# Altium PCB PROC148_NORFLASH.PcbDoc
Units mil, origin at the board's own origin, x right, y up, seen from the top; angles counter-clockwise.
Board outline 790 x 790 mil, 6 copper layers (Top Layer, GND1, Signal Layer 1, Signal Layer 2, PWR/GND2, Bottom Layer), stack 65.134 mil thick; 36 components, 63 nets, 233 pads, 102 vias.
Unrouted connection lines stored in the file: 1.
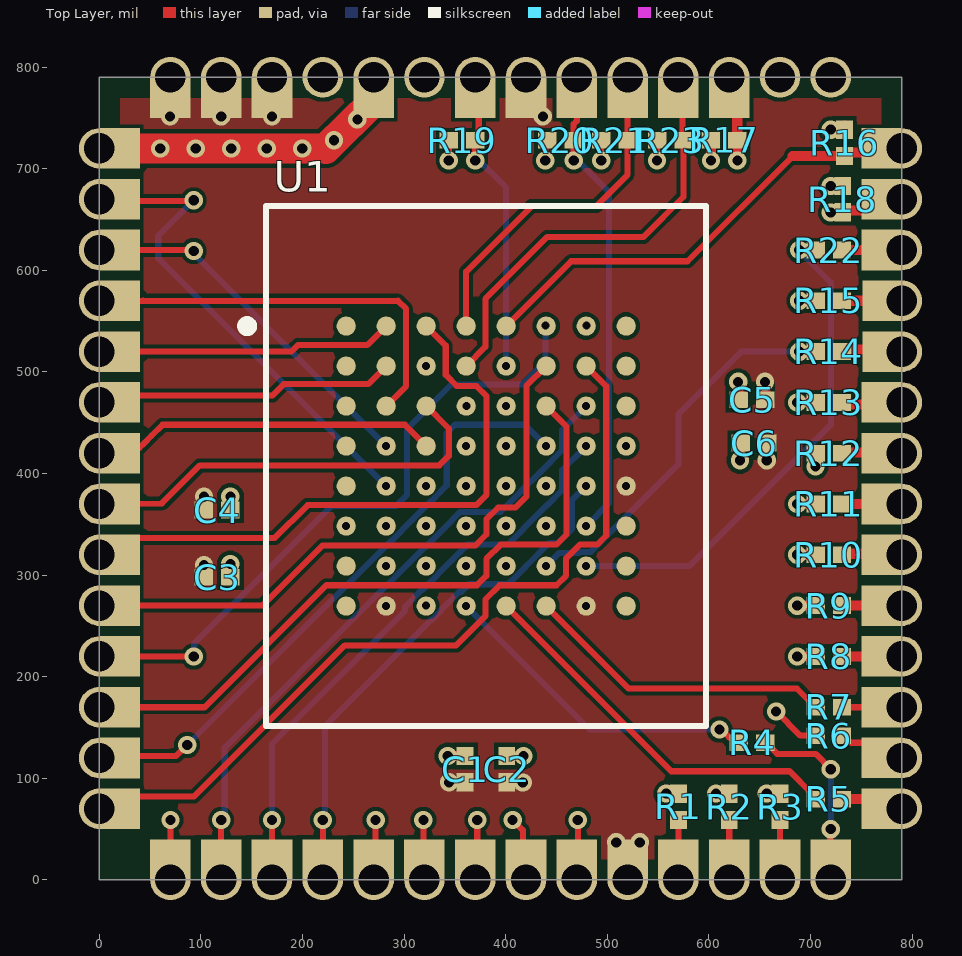
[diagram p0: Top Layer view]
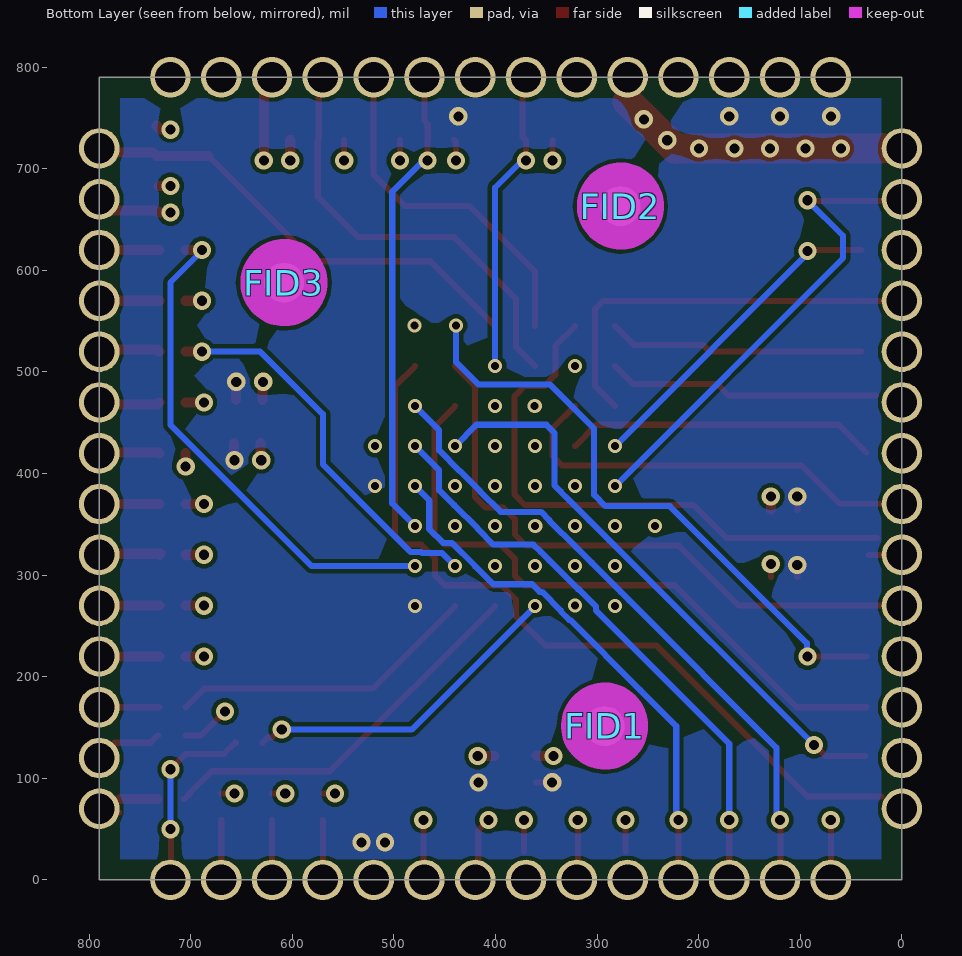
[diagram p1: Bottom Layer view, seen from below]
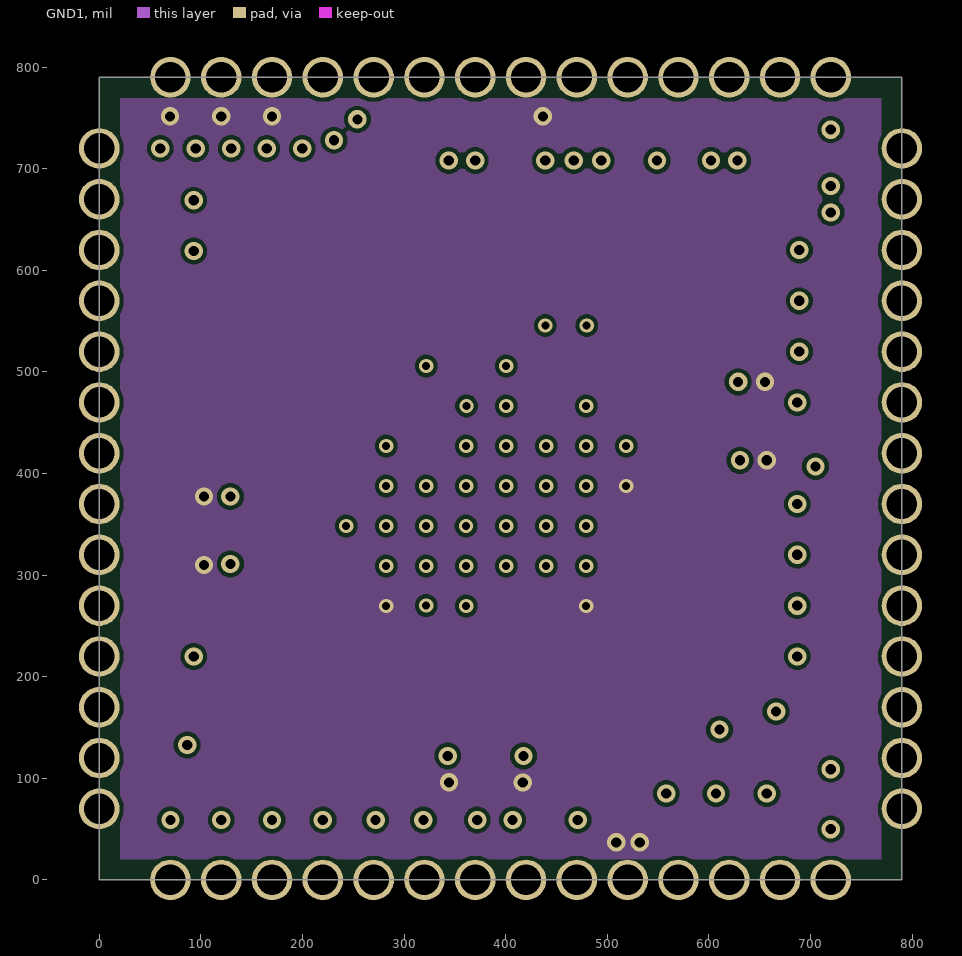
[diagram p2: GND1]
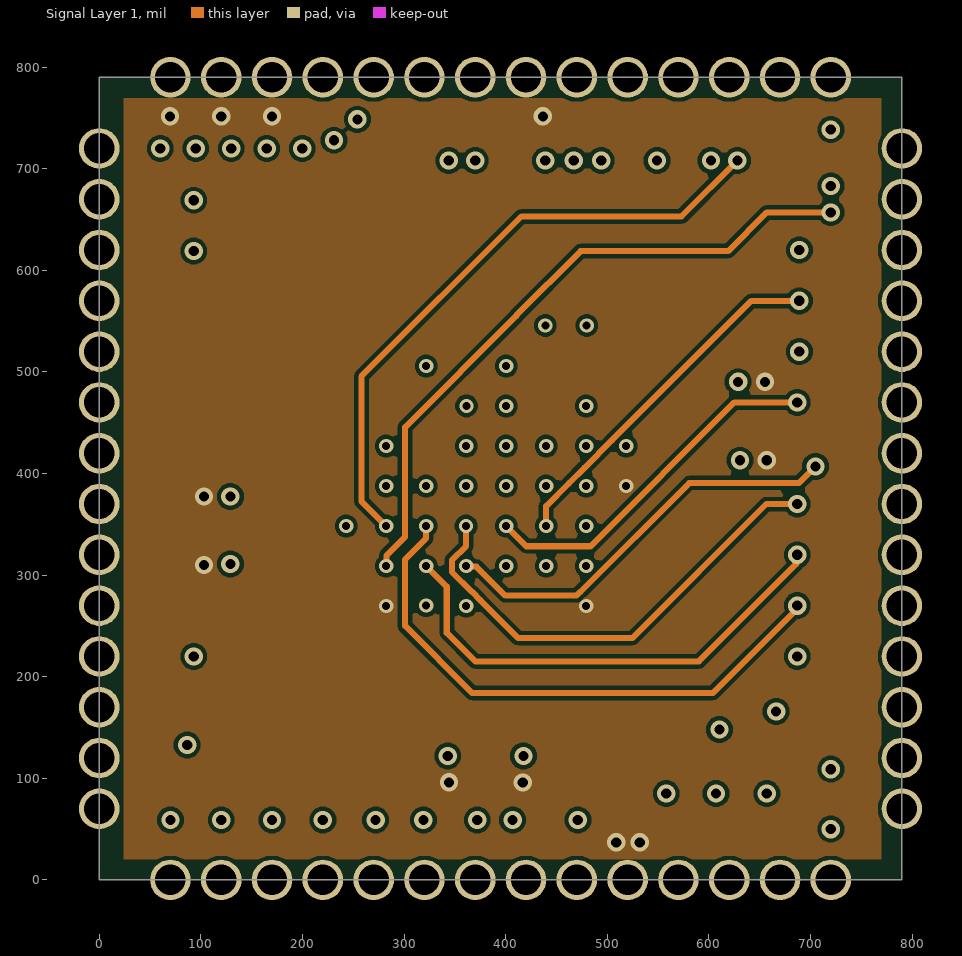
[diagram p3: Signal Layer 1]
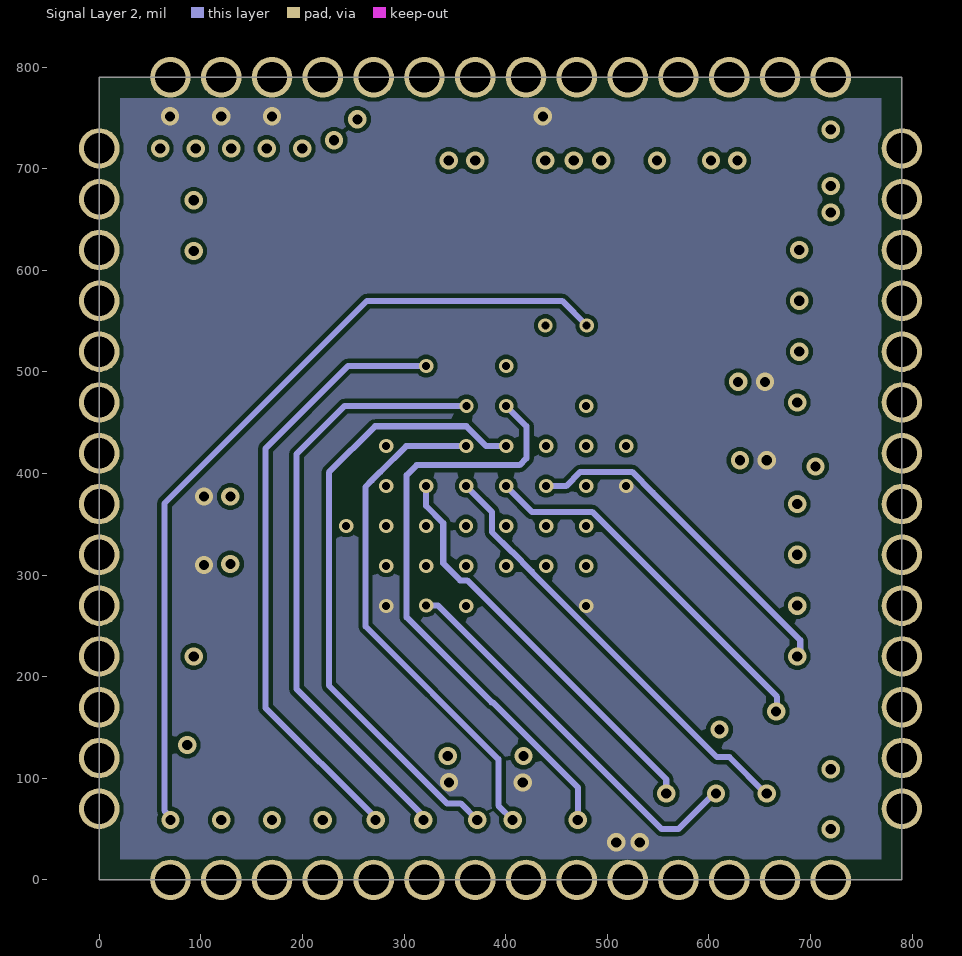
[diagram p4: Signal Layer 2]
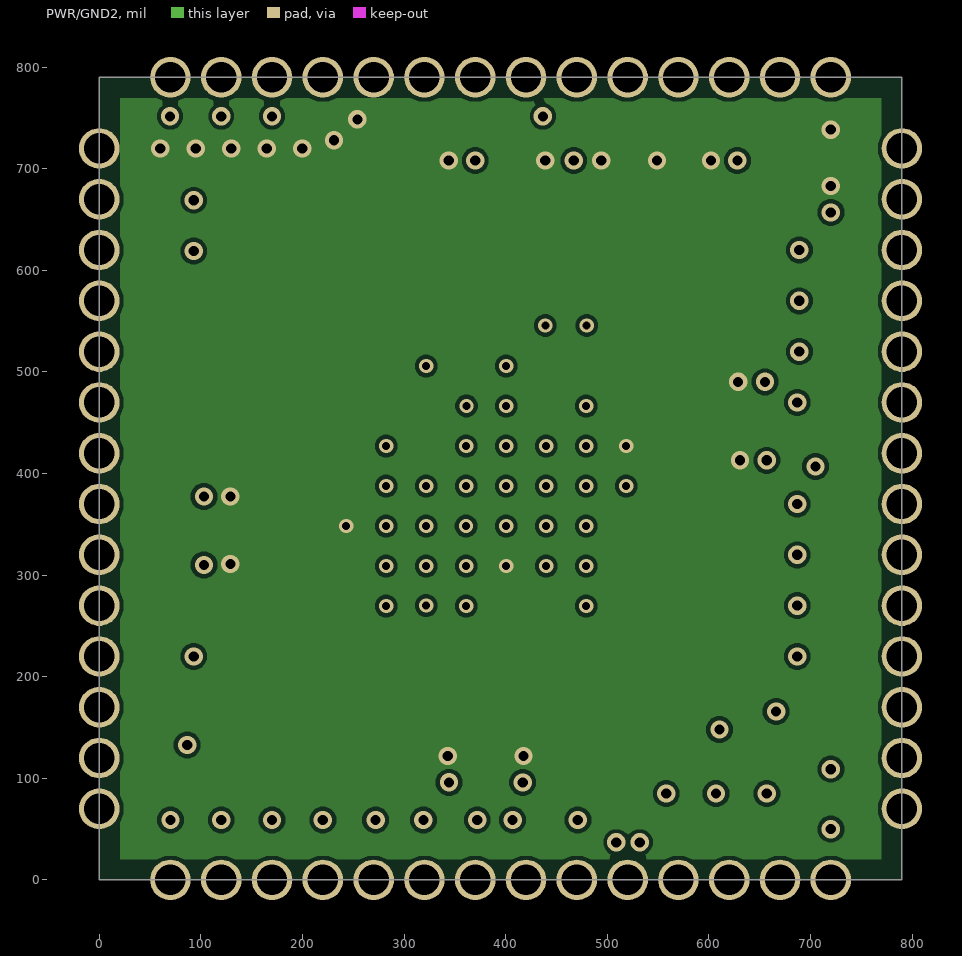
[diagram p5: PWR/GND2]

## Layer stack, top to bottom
Top Solder: solder mask 0.4, Solder Resist, Dk 3.5
Top Layer: signal copper 0.689
Dielectric 1: prepreg 3.7, FR-4, Dk 4.1
GND1: signal copper 0.689
Dielectric 3: prepreg 2.8, PP-006, Dk 4.1
Signal Layer 1: signal copper 0.689
Dielectric1: core 48, FR-4, Dk 4.8
Signal Layer 2: signal copper 0.689
Dielectric 4: prepreg 2.8, PP-006, Dk 4.1
PWR/GND2: signal copper 0.689
Dielectric 2: prepreg 3.7, FR-4, Dk 4.1
Bottom Layer: signal copper 0.689
Bottom Solder: solder mask 0.4, Solder Resist, Dk 3.5

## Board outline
0,0 790,0 790,790 0,790

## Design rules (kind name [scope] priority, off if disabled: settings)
AcuteAngle [All] p1: minimum=4.50000000000000E+0001 checktracksonly=FALSE
AssemblyTestPointUsage [All] p1: valid=2
BoardOutlineClearance BoardOutlineClearance_MountingHoles [OnCopper and InComponentClass('Mounting Holes')] p1: gap=39.37 ignorepadtopadclearanceinfootprint=FALSE
BoardOutlineClearance BoardOutlineClearance_Poly [OnCopper and IsPoly] p2: gap=20 ignorepadtopadclearanceinfootprint=FALSE
BoardOutlineClearance [OnCopper and Not InComponentClass('Logo') and not InComponentClass('FiducialMark') and not InRegion(1000,500,4000,800) and not InPoly] p3: gap=40 ignorepadtopadclearanceinfootprint=FALSE
Clearance Clearance_Keepouts [((IsTrack Or IsArc) And Not InPoly) And IsFree and IsKeepOut vs ((IsTrack Or IsArc) And Not InPoly) And IsFree and IsKeepOut] p1: gap=0 ignorepadtopadclearanceinfootprint=FALSE
Clearance Clearance_Poly [InPolygon] p2: gap=4 ignorepadtopadclearanceinfootprint=TRUE except(10: Arc-Arc Arc-Track Arc-SMDPad Arc-THPad Arc-Text Arc-Hole Track-Track Track-SMDPad Track-THPad Track-Text Track-Hole SMDPad-SMDPad SMDPad-THPad SMDPad-Text SMDPad-Hole THPad-THPad THPad-Text THPad-Hole Text-Text Text-Hole)
Clearance Clearance_FiducialMark [IsKeepOut and InComponentClass('FiducialMark') vs IsPad and InComponentClass('FiducialMark')] p3: gap=0 ignorepadtopadclearanceinfootprint=FALSE
Clearance [All] p4: gap=4 ignorepadtopadclearanceinfootprint=TRUE
ComponentClearance ComponentClearance_MountingHoles_FiducialMarks [InComponentClass('Mounting Holes') vs InComponentClass('FiducialMark')] p1: gap=50 collisioncheckmode=3 verticalgap=10 showdistances=FALSE
ComponentClearance ComponentClearance_Shunt [InComponentClass('Header') vs InComponentClass('Shunt')] p2: gap=0 collisioncheckmode=3 verticalgap=0 showdistances=FALSE
ComponentClearance ComponentClearance_Logo [InComponentClass('Logo')] p3: gap=30 collisioncheckmode=3 verticalgap=10 showdistances=FALSE
ComponentClearance ComponentClearance_ScrewToNut [(HasFootprint('NY PMS 440 0025 PH')) vs (HasFootprint('Keystone_1902C'))] p4: gap=5 collisioncheckmode=3 verticalgap=10 showdistances=FALSE
ComponentClearance ComponentClearance_MountingHoles [InComponentClass('Mounting Holes')] p5: gap=100 collisioncheckmode=3 verticalgap=100000 showdistances=FALSE
ComponentClearance ComponentClearance_SmallPassives [HasFootprint('0201*') or HasFootprint('0402*') or HasFootprint('0508') or HasFootprint('0603*') or HasFootprint('0612') or HasFootprint('0805*') or HasFootprint('0815*') or HasFootprint('0830*') or HasFootprint('1206*') or HasFootprint('1210*') or HasFootprint('1808*') or HasFootprint('1812*') or HasFootprint('1825*') or HasFootprint('2010*') or HasFootprint('2220*') or HasFootprint('2225*') or HasFootprint('2512*') or HasFootprint('2728*') or HasFootprint('3518*') vs HasFootprint('0201*') or HasFootprint('0402*') or HasFootprint('0508') or HasFootprint('0603*') or HasFootprint('0612') or HasFootprint('0805*') or HasFootprint('0815*') or HasFootprint('0830*') or HasFootprint('1206*') or HasFootprint('1210*') or HasFootprint('1808*') or HasFootprint('1812*') or HasFootprint('1825*') or HasFootprint('2010*') or HasFootprint('2220*') or HasFootprint('2225*') or HasFootprint('2512*') or HasFootprint('2728*') or HasFootprint('3518*')] p6: gap=14.96 collisioncheckmode=3 verticalgap=10 showdistances=FALSE
ComponentClearance ComponentClearance_THtoSMT [IsThruComponent vs IsSMTComponent] p7: gap=30 collisioncheckmode=3 verticalgap=30 showdistances=FALSE
ComponentClearance ComponentClearance_THtoTH [IsThruComponent vs IsThruComponent] p8: gap=20 collisioncheckmode=3 verticalgap=30 showdistances=FALSE
ComponentClearance [All] p9: gap=20 collisioncheckmode=3 verticalgap=10 showdistances=FALSE
DiffPairsRouting [All] p1: maxlimit=100 minlimit=10 mostfreqgap=10 toplayer_minwidth=15 toplayer_maxwidth=15 toplayer_prefwidth=15 midlayer1_minwidth=15 midlayer1_maxwidth=15 midlayer1_prefwidth=15 midlayer2_minwidth=15 midlayer2_maxwidth=15 midlayer2_prefwidth=15 midlayer3_minwidth=15 midlayer3_maxwidth=15 midlayer3_prefwidth=15 midlayer4_minwidth=15 midlayer4_maxwidth=15 midlayer4_prefwidth=15 bottomlayer_minwidth=15 bottomlayer_maxwidth=15 bottomlayer_prefwidth=15 maxuncoupledlength=1000
FabricationTestPointUsage TestPointUsage [All] p1: valid=2 allowmultiple=FALSE
FabricationTestpoint Testpoint [All] p1: side=3 testpointundercomponent=TRUE minsize=40 maxsize=100 preferedsize=60 minholesize=0 maxholesize=40 preferedholesize=32 testpointgrid=1 allowsidetop=TRUE allowsidebottom=TRUE usegrid=TRUE gridtolerance=0.01
FanoutControl Fanout_LCC [IsLCC] p1: bgadir=Out bgaviamode=Centered fanoutstyle=Auto fanoutdirection=Alternating viagrid=1 // Fanout_LCC (Default Rule)
FanoutControl Fanout_BGA [IsBGA] p2: bgadir=Out bgaviamode=Centered fanoutstyle=Auto fanoutdirection=Alternating viagrid=1 // Fanout_BGA (Default Rule)
FanoutControl Fanout_Default [All] p4: bgadir=Out bgaviamode=Centered fanoutstyle=Auto fanoutdirection=Alternating viagrid=1 // Fanout_Default (Default Rule)
FanoutControl Fanout_Small [(CompPinCount < 5)] p5: bgadir=Out bgaviamode=Centered fanoutstyle=Auto fanoutdirection=OutThenIn viagrid=1 // Fanout_Small (Default Rule)
HoleSize [All] p1: absolutevalues=TRUE maxlimit=251 minlimit=7 maxpercent=80.000 minpercent=20.000
HoleToHoleClearance [All] p1: gap=6 allowstackedmicrovias=TRUE
MinimumAnnularRing MinimumAnnularRing_ThermalPadVias [IsVia and InAnyComponent] p1: minimumring=5.91
MinimumAnnularRing [All] p2: minimumring=3
MinimumSolderMaskSliver MinimumSolderMaskSliver_Logo [InComponentClass('Logo') vs InComponentClass('Logo')] p1: minsoldermaskwidth=0.7
MinimumSolderMaskSliver [All] p2: minsoldermaskwidth=3
PlaneConnect [All] p1: planeconnectstyle=Relief reliefexpansion=10 reliefentries=4 reliefconductorwidth=10 reliefairgap=10
PolygonConnect [All] p1: connectstyle=Direct reliefconductorwidth=10 reliefentries=4 polygonreliefangle="90 Angle" airgapwidth=10
RoutingVias ThermalPadVias [IsVia and InAnyComponent] p1: holewidth=7.87 width=19.68 viastyle="Through Hole" minholewidth=7.87 minwidth=19.68 maxholewidth=12.99 maxwidth=23.62
RoutingVias [All] p2: holewidth=16 width=34 viastyle="Through Hole" minholewidth=7.87 minwidth=14 maxholewidth=40 maxwidth=65
SilkToBoardRegionClearance [Not ((IsComment or IsDesignator) And (Hide <> 'False')) and not InRegion(1000,500,4000,800)] p1:
SilkToSilkClearance SilkToSilkClearance_Pb-FreeLogo [(HasFootprint('Pb-Free_Overlay_Medium') OR HasFootprint('Pb-Free_Overlay_Small')) vs (HasFootprint('Pb-Free_Overlay_Medium') OR HasFootprint('Pb-Free_Overlay_Small'))] p1: silktosilkclearance=0
SilkToSilkClearance [All] p2: silktosilkclearance=3.94
SilkToSolderMaskClearance SilkToComponentPadClearance [(IsPad or IsFill or IsRegion) and InAnycomponent] p1: minsilkscreentomaskgap=5 clearancetoexposedcopper=TRUE
SilkToSolderMaskClearance "Silk to Solder Mask Opening" [All] p2: minsilkscreentomaskgap=3 clearancetoexposedcopper=FALSE
SolderMaskExpansion [All] p1: expansion=1.97 istentingtop=FALSE
UnRoutedNet [All] p1: checkbadconnections=TRUE
Width [All] p1: maxlimit=100 minlimit=6 preferedwidth=10 checkconnectedcopper=TRUE
13 further rules are at their usual default settings.

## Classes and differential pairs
component class PROC148_NORFLASH: C1 C2 C3 C4 C5 C6 R1 R2 R3 R4 R5 R6 R7 R8 R9 R10 R11 R12 R13 R14 R15 R16 R17 R19 R20 R21 R22 R23 U1
component class PROC148_NORFLASH_Hardware: FID1 FID2 FID3 ZZ2 ZZ3 ZZ4
component class FiducialMark: FID1 FID2 FID3
component class AssemblyNote: ZZ2 ZZ3 ZZ4

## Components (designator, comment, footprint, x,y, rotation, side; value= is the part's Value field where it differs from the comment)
C1 "GRM033R61C104KE84D" 0201_033 360,109 r270 top value=0.1uF
C2 "GRM033R61C103KA12D" 0201_033 401,109 r270 top value=0.01uF
C3 "GRM033R61C103KA12D" 0201_033 116,298 r180 top value=0.01uF
C4 "GRM033R61C104KE84D" 0201_033 116,364 r180 top value=0.1uF
C5 "GRM033R61C103KA12D" 0201_033 642.47,472.53 r0 top value=0.01uF
C6 "GRM033R61C104KE84D" 0201_033 644.48,430 r0 top value=0.1uF
FID1 "Fiducial" Fiducial10-20 292.6,151.41 r180 bottom
FID2 "Fiducial" Fiducial10-20 277.05,663.22 r180 bottom
FID3 "Fiducial" Fiducial10-20 608.24,587.88 r180 bottom
R1 "ERJ-1GNJ220C" 0201 570,72 r270 top value=22
R2 "ERJ-1GNJ220C" 0201 620,72 r270 top value=22
R3 "ERJ-1GNJ220C" 0201 670,72 r270 top value=22
R4 "ERJ-1GNJ220C" 0201 642.47,135.01 r0 top value=22
R5 "ERJ-1GNJ220C" 0201 718,79.5 r0 top value=22
R6 "ERJ-1GNJ220C" 0201 718,142 r0 top value=22
R7 "ERJ-1GNJ220C" 0201 718,170 r0 top value=22
R8 "ERJ-1GNJ220C" 0201 718,220 r0 top value=22
R9 "ERJ-1GNJ220C" 0201 718,270 r0 top value=22
R10 "ERJ-1GNJ220C" 0201 718,320 r0 top value=22
R11 "ERJ-1GNJ220C" 0201 718,370 r0 top value=22
R12 "ERJ-1GNJ220C" 0201 718,420 r0 top value=22
R13 "ERJ-1GNJ220C" 0201 718,470 r0 top value=22
R14 "ERJ-1GNJ220C" 0201 718,520 r0 top value=22
R15 "ERJ-1GNJ220C" 0201 718,570 r0 top value=22
R16 "RC0201JS-7D10KL" 0201 733.51,725.49 r90 top value=10k
R17 "RC0201JS-7D10KL" 0201 615,728 r180 top value=10k
R18 "RC0201JS-7D10KL" 0201 731.71,670 r90 top value=10k
R19 "RC0201JS-7D10KL" 0201 357,728 r180 top value=10k
R20 "RC0201JS-7D10KL" 0201 453.74,728 r180 top value=10k
R21 "RC0201JS-7D10KL" 0201 507,728 r180 top value=10k
R22 "ERJ-1GNJ220C" 0201 718,620 r0 top value=22
R23 "RC0201JS-7D10KL" 0201 562,728 r180 top value=10k
U1 "MT28EW256ABA1LPC-0SIT" FP-MT28EW256ABA1LPC-0SIT_LBGA64-IPC_C 380.8,407.32 r0 top
ZZ2 "These assemblies are ESD sensitive, ESD precautions shall be observed." AssemblyNote -81,2104 r0 top
ZZ3 "These assemblies must be clean and free from flux and all contaminants. Use of no clean flux is not acceptable." AssemblyNote -81,2004 r0 top
ZZ4 "These assemblies must comply with workmanship standards IPC-A-610 Class 2, unless otherwise specified." AssemblyNote -81,1904 r0 top

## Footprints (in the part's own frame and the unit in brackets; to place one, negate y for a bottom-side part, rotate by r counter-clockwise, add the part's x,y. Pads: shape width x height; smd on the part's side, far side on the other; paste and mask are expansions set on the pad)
0201 [mm] "Data from Kemet datasheet CC101_COM dated 7/28/11"
  rect 0.46x0.42 smd mask+0.048: 1(-0.33,0) 2(0.33,0)
  body extent -0.31,-0.16 0.31,0.16, height 0.26
0201_033 [mm] "SMD, 2-Leads, Height 0.33mm"
  rect 0.46x0.42 smd mask+0.048: 1(-0.33,0) 2(0.33,0)
  body extent -0.31,-0.16 0.31,0.16, height 0.33
AssemblyNote [mil] "Assembly Note"
Fiducial10-20 [mm]
  round 1 smd mask+0.5: 1(0,0)
  Top Layer keep-out circle w1.178: c0,0 r0.5
FP-MT28EW256ABA1LPC-0SIT_LBGA64-IPC_C [mm]
  round 0.48 smd paste+0 mask+0: A1(-3.5,3.5) A2(-2.5,3.5) A3(-1.5,3.5) A4(-0.5,3.5) A5(0.5,3.5) A6(1.5,3.5) A7(2.5,3.5) A8(3.5,3.5) B1(-3.5,2.5) B2(-2.5,2.5) B3(-1.5,2.5) B4(-0.5,2.5) B5(0.5,2.5) B6(1.5,2.5) B7(2.5,2.5) B8(3.5,2.5) C1(-3.5,1.5) C2(-2.5,1.5) C3(-1.5,1.5) C4(-0.5,1.5) C5(0.5,1.5) C6(1.5,1.5) C7(2.5,1.5) C8(3.5,1.5) D1(-3.5,0.5) D2(-2.5,0.5) D3(-1.5,0.5) D4(-0.5,0.5) D5(0.5,0.5) D6(1.5,0.5) D7(2.5,0.5) D8(3.5,0.5) E1(-3.5,-0.5) E2(-2.5,-0.5) E3(-1.5,-0.5) E4(-0.5,-0.5) E5(0.5,-0.5) E6(1.5,-0.5) E7(2.5,-0.5) E8(3.5,-0.5) F1(-3.5,-1.5) F2(-2.5,-1.5) F3(-1.5,-1.5) F4(-0.5,-1.5) F5(0.5,-1.5) F6(1.5,-1.5) F7(2.5,-1.5) F8(3.5,-1.5) G1(-3.5,-2.5) G2(-2.5,-2.5) G3(-1.5,-2.5) G4(-0.5,-2.5) G5(0.5,-2.5) G6(1.5,-2.5) G7(2.5,-2.5) G8(3.5,-2.5) H1(-3.5,-3.5) H2(-2.5,-3.5) H3(-1.5,-3.5) H4(-0.5,-3.5) H5(0.5,-3.5) H6(1.5,-3.5) H7(2.5,-3.5) H8(3.5,-3.5)
  silkscreen extent -6.1,-6.5 5.5,6.5, body extent -5.6,-6.6 5.6,6.6, height 0.25

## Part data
C1 C4 C6: library part CMP-0009717-2, "CAP, CERM, 0.1 uF, 16 V, +/- 10%, X5R, 0201", Cap_Case=0201, Manufacturer=MuRata, Supplier Part Number 1=490-9985-1-ND, TempCo=X5R, Tolerance_%=10%, Value1=Unknown, Value2=16V, ValueDisplayed=0.1uF
C2 C3 C5: library part CMP-0009716-1, "CAP, CERM, 0.01 uF, 16 V, +/- 10%, X5R, 0201", Cap_Case=0201, Manufacturer=MuRata, Supplier Part Number 1=490-7223-1-ND, TempCo=X5R, Tolerance_%=10%, Value1=Unknown, Value2=16V, ValueDisplayed=0.01uF
FID1 FID2 FID3: library part CMP-0077181-1, "Fiducial mark.  There is nothing to buy or mount.", Manufacturer=N/A
R1 R2 R3 R4 R5 R6 R7 R8 R9 R10 R11 R12 R13 R14 R15 R22: library part CMP-0027015-2, "RES, 22, 5%, 0.05 W, AEC-Q200 Grade 1, 0201", Manufacturer=Panasonic, Power_W=50mW, Supplier Part Number 1=ERJ-1GNJ220C-ND, TempCo="200 ppm/C", Tolerance_%=5%, Value2=0.05W, Value_Code=22R0, ValueDisplayed=22
R16 R17 R18 R19 R20 R21 R23: library part CMP-0027260-1, "RES, 10 k, 5%, 0.05 W, 0201", Manufacturer="Yageo America", Power_W=50mW, Supplier Part Number 1=603-RC0201JS-7D10KL, TempCo="200 ppm/C", Tolerance_%=5%, Value2=0.05W, Value_Code=10k0, ValueDisplayed=10k
U1: library part CMP-0095868-1, "FLASH - NOR Memory IC 256Mb (32M x 8, 16M x 16) Parallel 75 ns 64-LBGA (11x13)", Digikey Part Number=557-1782-ND, Manufacturer=Micron, Max Supply Voltage=3.6V, Min Supply Voltage=1.65V, Mouser Part Number=340-284805-TRAY, Operating Temperature Range="-40°C to +85°C"
ZZ2: library part CMP-0077236-1
ZZ3: library part CMP-0077237-1
ZZ4: library part CMP-0077238-1

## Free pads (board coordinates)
  round 40 hole 30: 3(0,70) 3(0,120) 3(0,170) 3(0,220) 3(0,270) 3(0,320) 3(0,370) 3(0,420) 3(0,470) 3(0,520) 3(0,570) 3(0,620) 3(0,670) 3(0,720) 3(70,0) 3(70,790) 3(120,0) 3(120,790) 3(170,0) 3(170,790) 3(220,0) 3(220,790) 3(270,0) 3(270,790) 3(320,0) 3(320,790) 3(370,0) 3(370,790) 3(420,0) 3(420,790) 3(470,0) 3(470,790) 3(520,0) 3(520,790) 3(570,0) 3(570,790) 3(620,0) 3(620,790) 3(670,0) 3(670,790) 3(720,0) 3(720,790) 3(790,70) 3(790,120) 3(790,170) 3(790,220) 3(790,270) 3(790,320) 3(790,370) 3(790,420) 3(790,470) 3(790,520) 3(790,570) 3(790,620) 3(790,670) 3(790,720)
  rect 40x40 smd mask+1.9: 4(19.86,720) 4(20,70) 4(20,120) 4(20,170) 4(20,220) 4(20,270) 4(20,320) 4(20,370) 4(20,420) 4(20,470) 4(20,520) 4(20,570) 4(20,620) 4(20,670) 4(70,20) 4(70,770) 4(120,20) 4(120,770) 4(170,20) 4(170,770) 4(220,20) 4(270,20) 4(270,770) 4(320,20) 4(370,20) 4(370,770) 4(420,20) 4(420,770) 4(470,20) 4(470,770) 4(519.99,770) 4(520,20) 4(570,20) 4(570,770) 4(620,20) 4(620,770) 4(670,20) 4(720,20) 4(770,70) 4(770,120.14) 4(770,170) 4(770,220) 4(770,270) 4(770,320) 4(770,370) 4(770,420) 4(770,470) 4(770,620) 4(770,670) 4(770,720) 4(771,520) 4(771,570)

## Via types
v1: diameter 18, hole 10, Top Layer to Bottom Layer, tented both sides, 65 vias
v2: diameter 14, hole 7.87, Top Layer to Bottom Layer, tented both sides, 37 vias

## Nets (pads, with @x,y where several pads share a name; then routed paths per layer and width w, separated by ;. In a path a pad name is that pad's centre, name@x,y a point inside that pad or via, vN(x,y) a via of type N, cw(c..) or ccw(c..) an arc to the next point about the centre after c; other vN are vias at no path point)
GND: C1.2 C2.2 C3.2 C4.2 C5.2 C6.2 pad.3@70,790 pad.3@120,790 pad.3@170,790 pad.3@420,790 pad.3@520,0 pad.4@70,770 pad.4@120,770 pad.4@170,770 pad.4@420,770 pad.4@520,20 U1.E8 U1.H2 U1.H7 | length 71.5
  Top Layer w6: C3.2 v1(103,310) ; C4.2 v1(103.01,377.29) ; v1(344.25,96.01) C1.2
  Top Layer w10: C5.2 v1@655.47,488 ; v1@657.47,415 C6.2
  other v1: 508.84,37 532,37 416.75,95.93 657,413 655.23,490.24 69.66,751.54 120,751.54 170,751.54 436.59,751.54
  other v2: 282.37,269.52 479.22,269.52 518.59,387.63
GPMC0_A0_MUX: pad.3@0,670 pad.4@20,670 U1.E2 | length 462.3
  Top Layer w6: pad.4@19.86,668.09 92.09,668.09 v1(93,669)
  Bottom Layer w6: v1(93,669) 58,634 58,612 v2(282.37,387.63)
GPMC0_A1_MUX: pad.3@0,620 pad.4@20,620 U1.D2 | length 323
  Top Layer w6: 40,619.91 92.09,619.91 v1(93,619)
  Bottom Layer w6: v1@91.68,617.69 v2(282.37,427)
GPMC0_A2_MUX: pad.3@0,570 pad.4@20,570 U1.C2 | length 389.1
  Top Layer w6: pad.4@20,570 293.91,570.09 302,562 302,486 U1.C2
GPMC0_A3_MUX: pad.3@0,520 pad.4@20,520 U1.A2 | length 252.8
  Top Layer w6: 40,520.09 189.15,520 195.47,526.32 263.58,526.32 U1.A2
GPMC0_A4_MUX: pad.3@0,470 pad.4@20,470 U1.B2 | length 268.9
  Top Layer w6: pad.4@25.49,476.77 170.28,476.77 181.51,488 264.63,488 U1.B2
GPMC0_A5_MUX: pad.3@0,420 pad.4@20,420 U1.D3 | length 306.9
  Top Layer w6: pad.4@34.86,420.62 39.55,425.31 44.24,430 51.4,437.16 62.24,448 300.74,448 U1.D3
GPMC0_A6_MUX: pad.3@0,370 pad.4@20,370 U1.C3 | length 402.1
  Top Layer w6: pad.4@20,370 61.61,370.6 99.05,408 334.65,408 344.01,417.36 344.01,444.33 321.74,466.6 U1.C3
GPMC0_A7_MUX: pad.3@0,320 pad.4@20,320 U1.A3 | length 609.6
  Top Layer w6: pad.4@0,320 20,320 pad.4@32.82,320 ; pad.4@24,336.4 172.37,336.4 204.97,369 371,369 381.19,379.19 381.19,476.18 371.2,486.17 351.83,486.17 341,497 341,525.85 U1.A3
GPMC0_A8_MUX: pad.3@0,270 pad.4@20,270 U1.B6 | length 590.1
  Top Layer w6: pad.4@20,270 160.5,270 219.5,329 370,329 381,340 381,355 392.41,366.41 409.41,366.41 420.34,377.34 420.34,486.23 U1.B6
GPMC0_A9_MUX: pad.3@0,220 pad.4@20,220 U1.A6 | length 605.3
  Top Layer w6: pad.4@35,220 v1(93,220)
  Bottom Layer w6: v1(93,220) 93.48,220.48 93.48,232.97 228.51,368 291.9,368 303,379.1 303,444.12 346.64,487.76 416.87,487.76 439,509.89 v2(439,545.69)
GPMC0_A10_MUX: pad.3@0,170 pad.4@20,170 U1.C6 | length 639.8
  Top Layer w6: pad.4@35,170 103.6,170 223.6,290 371.59,290 381,299.41 381,316 395,330 450,330 460,340 460,446.22 U1.C6
GPMC0_A11_MUX: pad.3@0,120 pad.4@20,120 U1.D6 | length 578.2
  Top Layer w6: pad.4@36,122 75.68,122 v1(86.5,132.82)
  Bottom Layer w6: v1(86.5,132.82) 287.94,334.26 288.17,334.26 307.74,353.83 307.74,354.06 327.31,373.63 327.54,373.63 335.74,381.83 335.74,382.06 342,388.32 342,440.06 349.94,448 418.85,448 v2(439.85,427)
GPMC0_A12_MUX: pad.3@0,70 pad.4@20,70 U1.B7 | length 779.4
  Top Layer w6: pad.4@20.39,82.27 93.27,82.27 241.8,230.8 351.19,230.8 380,259.61 380,276 394,290 450,290 459.54,299.54 459.54,316.54 473,330 490,330 499,339 499,485.96 U1.B7
GPMC0_A13_MUX: pad.3@70,0 pad.4@70,20 U1.A7 | length 859.7
  Top Layer w6: pad.4@70,20 v1@70,53
  Signal Layer 2 w6: v1@70,53 v1@73,56 ; v1(70,59) 70,62.25 64,68.25 64,370.49 263.51,570 455.46,570 v2(479.77,545.69)
GPMC0_A14_MUX: pad.3@120,0 pad.4@120,20 U1.C7 | length 619
  Top Layer w6: pad.4@119.69,20 119.69,58.69 v1(120,59)
  Bottom Layer w6: v1(120,59) 120,61.16 123.51,64.68 123.51,130.24 268.37,275.09 268.37,275.32 276.57,283.52 276.8,283.52 305.3,312.02 305.3,312.24 320.4,327.35 320.63,327.35 347,353.72 347,354.06 355.2,362.26 394.91,362.26 414.88,382.23 414.88,382.46 434.85,402.43 435.08,402.43 455.44,422.79 455.44,442.59 v2(479.22,466.37)
GPMC0_A15_MUX: pad.3@170,0 pad.4@170,20 U1.D7 | length 558.8
  Top Layer w6: pad.4@170,20 v1(170,59)
  Bottom Layer w6: v1(170,59) 170,134.08 301,265.08 301,269.06 318.02,286.07 318.72,286.07 347.11,314.46 347.11,314.69 355.31,322.89 355.54,322.89 362.65,330 402.02,330 417.72,345.7 417.72,345.93 440.53,368.74 440.76,368.74 455.44,383.42 455.44,403.22 v2(479.22,427)
GPMC0_A16_MUX: pad.3@220,0 pad.4@220,20 U1.E7 | length 504.5
  Top Layer w6: pad.4@220,20 v1(220,59)
  Bottom Layer w6: v1(220,59) 222.13,61.13 222.13,151.47 257.34,186.67 326.66,256 327.54,256 335.74,264.2 335.74,265.08 354.18,283.52 356.52,283.52 364,291 402.11,291 406,294.89 406.28,294.89 420.17,308.78 420.17,309 442.97,331.81 451.66,331.81 465.22,345.37 465.22,373.63 v2(479.22,387.63)
GPMC0_A17_MUX: pad.3@270,0 pad.4@270,20 U1.B3 | length 631.4
  Top Layer w6: pad.4@272,27.96 v1(272,59)
  Signal Layer 2 w6: v1@272,61 163.53,169.47 163.53,424.53 244.74,505.74 v2(321.74,505.74)
GPMC0_A18_MUX: pad.3@320,0 pad.4@320,20 U1.C4 | length 633.9
  Top Layer w6: pad.4@319,20 v1(319,59)
  Signal Layer 2 w6: v1@319,63 194,188 194,419 241.52,466.52 v2(361.44,466.52)
GPMC0_A19_MUX: pad.3@370,0 pad.4@370,20 U1.D5 | length 643
  Top Layer w6: pad.4@372,27.96 v1(372,59)
  Signal Layer 2 w6: v1(372,59) 355.66,75.34 342.04,75.34 226,191.38 226,401.08 271.44,446.51 361.39,446.51 380.91,427 v2(400.48,427)
GPMC0_A20_MUX: pad.3@420,0 pad.4@420,20 U1.D4 | length 546.9
  Top Layer w6: v1(406.85,59) 417,48.85 pad.4@417,20
  Signal Layer 2 w6: v2(361.11,427) 302.17,427 276.8,401.63 276.57,401.63 268.37,393.43 268.37,393.2 262,386.83 262,249.49 392.75,118.74 392.75,73.1 v1(406.85,59)
GPMC0_A21_MUX: pad.3@470,0 pad.4@470,20 U1.C5 | length 633.3
  Top Layer w6: pad.4@471,20 v1(471,59)
  Signal Layer 2 w6: v2(400.48,466.37) 420.34,446.51 420.34,414.86 413.7,408.22 312.34,408.22 302.48,398.36 302.48,258.48 386.16,174.8 387.32,174.8 471,91.13 v1(471,59)
GPMC0_AD0_MUX: pad.3@570,0 pad.4@570,20 R1.2 | length 39
  Top Layer w6: pad.4@570,20 R1.2
GPMC0_AD1_MUX: pad.3@620,0 pad.4@620,20 R2.2 | length 39
  Top Layer w6: pad.4@620,20 R2.2
GPMC0_AD2_MUX: pad.3@670,0 pad.4@670,20 R3.2 | length 59
  Top Layer w6: pad.4@670,0 R3.2
GPMC0_AD3_MUX: pad.3@720,0 pad.4@720,20 R4.2 | length 164.5
  Top Layer w6: R4.2 656.25,135.01 667.26,124 705,124 v1(720,109) ; pad.4@719.45,20 719.45,49.45 v1(720,50)
  Bottom Layer w6: v1(720,50) v1(720,109)
GPMC0_AD4_MUX: pad.3@790,70 pad.4@770,70 R5.2 | length 56.6
  Top Layer w6: pad.4@770,66.48 pad.3@790,66.48
  Top Layer w10: R5.2@732.99,79.5 pad.4@769.61,79.5
GPMC0_AD5_MUX: pad.3@790,120 pad.4@770,120.14 R6.2 | length 67.1
  Top Layer w6: R6.2@731.99,142 732.78,142 739.77,135.01 774.99,135.01 pad.3@790,120
GPMC0_AD6_MUX: pad.3@790,170 pad.4@770,170 R7.2 | length 59
  Top Layer w6: R7.2 pad.3@790,170
GPMC0_AD7_MUX: pad.3@790,220 pad.4@770,220 R8.2 | length 59
  Top Layer w10: R8.2 pad.3@790,220
GPMC0_AD8_MUX: pad.3@790,270 pad.4@770,270 R9.2 | length 59
  Top Layer w10: R9.2 pad.3@790,270
GPMC0_AD9_MUX: pad.3@790,320 pad.4@770,320 R10.2 | length 60.8
  Top Layer w10: R10.2@729.99,321 R10.2 731.99,321 pad.3@790,321
GPMC0_AD10_MUX: pad.3@790,370 pad.4@770,370 R11.2 | length 59
  Top Layer w10: R11.2 pad.3@790,370
GPMC0_AD11_MUX: pad.3@790,420 pad.4@770,420 R12.2 | length 59.2
  Top Layer w10: R12.2 731.52,420.53 pad.3@790,420.53
GPMC0_AD12_MUX: pad.3@790,470 pad.4@770,470 R13.2 | length 59.8
  Top Layer w10: R13.2 732.99,468 pad.3@790,468
GPMC0_AD13_MUX: pad.3@790,520 pad.4@771,520 R14.2 | length 59.8
  Top Layer w10: R14.2 732.99,522 pad.4@790,522
GPMC0_AD14_MUX: pad.3@790,570 pad.4@771,570 R15.2 | length 59
  Top Layer w10: R15.2 pad.4@790,570
GPMC0_AD15_MUX: pad.3@790,620 pad.4@770,620 R22.2 | length 59
  Top Layer w10: R22.2 pad.3@790,620
GPMC0_CSN0_MUX: pad.3@620,790 pad.4@620,770 R17.1 U1.F2 | length 700.7
  Top Layer w10: pad.3@620,790 627.99,782.01 R17.1 v1(628,708)
  Signal Layer 1 w6: v2(282.37,348.26) 258,372.63 258,495.63 415.37,653 573,653 v1(628,708)
GPMC0_OEN_REN_MUX: pad.3@790,670 pad.4@770,670 R18.1 U1.G2 | length 726.7
  Top Layer w10: v1(720,657.01) R18.1 733.7,659 779,659 pad.3@790,670
  Signal Layer 1 w6: v2(282.37,308.89) 282.64,309.16 282.64,319.25 301,337.61 301,445.63 410.52,555.15 410.52,555.65 473.88,619 619,619 657.01,657.01 v1(720,657.01)
GPMC0_WAIT0_MUX: pad.3@520,790 pad.4@519.99,770 R21.1 U1.A4 | length 347.9
  Top Layer w6: U1.A4 361.11,598.74 425.59,663.22 489.07,663.22 519.99,694.14 519.99,770 pad.3@519.99,790
GPMC0_WEN_MUX: pad.3@790,720 pad.4@770,720 R16.1 U1.A5 | length 460.3
  Top Layer w6: U1.A5 464.35,608.98 578.93,608.98 682.45,712.5
  Top Layer w10: 682.45,712.5 R16.1 737.01,716 pad.3@790,716
GPMC0_WPN_MUX: pad.3@570,790 pad.4@570,770 R23.1 U1.B4 | length 428.7
  Top Layer w6: U1.B4 380,524.63 380,571.89 441.11,633 535.74,633 574.99,672.26 R23.1 574,728.99 574,770 pad.3@574,790
HSEC_GPIO45: pad.3@470,790 pad.4@470,770 R20.1 U1.F7 | length 466.8
  Top Layer w6: v1@467,712 467,727.73 R20.1 466.73,743.73 470,747 pad.3@470,790
  Bottom Layer w6: v1@467,712 501.63,677.37 501.63,370.67 v2(479.22,348.26)
  other v1: 467,708
HSEC_GPIO46: pad.3@370,790 pad.4@370,770 R19.1 U1.B5 | length 298.3
  Top Layer w6: v1@370,712 R19.1 373.51,731.51 pad.3@373.51,790
  Bottom Layer w6: v1@370,712 400.48,681.52 v2(400.48,505.74)
  other v1: 370,708
NOR_D0: R1.1 U1.E3 | length 416.4
  Top Layer w6: v1(558,85) R1.1
  Signal Layer 2 w6: v2(321.74,387.63) 321.74,368.06 338.53,351.27 338.53,311.68 355.31,294.89 362,294.89 558,98.89 v1(558,85)
NOR_D1: R2.1 U1.H3 | length 403.9
  Top Layer w6: v1(607,85) R2.1
  Signal Layer 2 w6: v2(321.74,270) 333.51,270 553.51,50 570,50 605,85 v1(607,85)
NOR_D2: R3.1 U1.E4 | length 446
  Top Layer w6: v1(657,85) R3.1
  Signal Layer 2 w6: v2(361.11,387.63) 386.48,362.26 386.48,342.46 406.05,322.89 406.28,322.89 425.85,303.32 425.85,303.09 607.93,121.01 620,121.01 656.01,85 v1(657,85)
NOR_D3: R4.1 U1.H4 | length 324.7
  Top Layer w6: v1(610.36,148.01) 612.14,148.01 619.88,140.28 624.21,140.28 R4.1
  Bottom Layer w6: v2(361.11,269.52) 482.62,148.01 v1@610.93,148.01
NOR_D4: R5.1 U1.H5 | length 385.7
  Top Layer w6: U1.H5 563,107 679.51,107 700.95,85.56 700.95,84.77 706.22,79.5 R5.1@707.01,79.5
NOR_D5: R6.1 U1.E5 | length 415.9
  Top Layer w6: v1(666.2,165.83) 690.03,142 R6.1
  Signal Layer 2 w6: v2(400.48,387.63) 425.85,362.26 485.02,362.26 667.1,180.18 667.1,166.73 v1(666.2,165.83)
NOR_D6: R7.1 U1.H6 | length 306.4
  Top Layer w6: U1.H6 521.07,188.3 686.71,188.3 R7.1
NOR_D7: R8.1 U1.E6 | length 357.7
  Top Layer w10: v1@688.47,220 R8.1
  Signal Layer 2 w6: v2(439.85,387.63) 459.42,387.63 473.42,401.63 524.39,401.63 544.92,381.1 689.95,236.07 689.95,221.48 v1@688.47,220
  other v1: 687,220
NOR_D8: R9.1 U1.F3 | length 574.8
  Top Layer w10: v1@688.47,270 R9.1
  Signal Layer 1 w6: v2(321.74,348.26) 321.74,336.26 301,315.52 301,249.98 367.13,183.85 603.8,183.85 688.47,268.52 v1@688.47,270
  other v1: 687,270
NOR_D9: R10.1 U1.G3 | length 496.1
  Top Layer w10: v1@688.47,320 R10.1
  Signal Layer 1 w6: v2(321.74,308.89) 342,288.63 342,243.23 370.17,215.06 590.11,215.06 686.18,311.12 686.18,317.7 v1@688.47,320
  other v1: 687,320
NOR_D10: R11.1 U1.F4 | length 490.6
  Top Layer w10: v1@688.47,370 R11.1
  Signal Layer 1 w6: v2(361,348.26) 361,328.58 347.11,314.69 347.11,303.09 366.68,283.52 366.91,283.52 375.11,275.32 375.11,275.09 412.2,238 524.68,238 656.68,370 v1@688.47,370
  other v1: 687,370
NOR_D11: R12.1 U1.G4 | length 421.7
  Top Layer w10: v1(705,407) R12.1
  Signal Layer 1 w6: v2(361.11,308.89) 361.69,308.32 371.16,308.32 399.71,279.77 469.67,279.77 473.42,283.52 473.65,283.52 580.66,390.53 688.53,390.53 v1(705,407)
NOR_D12: R13.1 U1.F5 | length 371.4
  Top Layer w10: v1(687,470) R13.1
  Signal Layer 1 w6: v2(400.48,348.26) 420.28,328.46 483.6,328.46 625.14,470 v1(687,470)
NOR_D13: R14.1 U1.G6 | length 380.9
  Top Layer w10: v1(689,520) R14.1
  Bottom Layer w6: v2(439.85,308.89) 452.77,321.81 472.34,321.81 473.42,322.89 483.74,322.89 570,409.15 570,458.36 631.64,520 v1@688.47,520
NOR_D14: R15.1 U1.F6 | length 368.7
  Top Layer w10: v1(689,570) R15.1
  Signal Layer 1 w6: v2(439.85,348.26) 439.85,367.83 462.32,390.3 462.32,390.53 477.66,405.87 477.88,405.87 504.59,432.57 504.59,432.8 641.79,570 v1(689,570)
NOR_D15: R22.1 U1.G7 | length 503
  Top Layer w10: v1@686.81,620 R22.1
  Bottom Layer w6: v2(479.22,308.89) 580.89,308.89 720,448 720,588 688,620 v1@686.81,620
  other v1: 689,620
VDD_3V3_SYS: C1.1 C2.1 C3.1 C4.1 C5.1 C6.1 pad.3@0,720 pad.3@270,790 pad.4@19.86,720 pad.4@270,770 R16.2 R17.2 R18.2 R19.2 R20.2 R21.2 R23.2 U1.D8 U1.F1 U1.G5 | length 467.9
  Top Layer w6: C3.1 v1(129,311) ; v1@344.01,712.5 R19.2 ; v1@439,712 439,726.25 R20.2 ; v1@494.01,712.5 R21.2 ; v1@549.01,712.5 R23.2
  Top Layer w10: C4.1 v1(129,377.29) ; v1(343,122) 359.26,122 C1.1@359.63,122.37 ; U1.G5@400.48,306.48 v2(400.48,308.89) ; C2.1 v1(417.5,122) ; v1@602.01,712.5 R17.2 ; v1@629,488 629.24,487.76 629.24,472.78 C5.1 ; v1@631,415 631.24,415.24 631.24,429.76 C6.1 ; v1(720,682.99) R18.2 ; v1(720,738.48) 730.24,738.48 733.51,741.75 R16.2@733.51,742.49
  Top Layer w30: pad.4@19.86,720 223.07,719.76 pad.4@269.81,766
  other v1: 630.53,413 628.76,490.24 344.01,708 439,708 494.01,708 549.01,708 602.01,708 60,720 94.94,719.96 129.88,719.93 164.83,719.88 199.77,719.84 231,728 254,748.59
  other v2: 243,348.26 518.59,427
pads on no net: FID1.1 FID2.1 FID3.1 U1.A1 U1.A8 U1.B1 U1.B8 U1.C1 U1.C8 U1.D1 U1.E1 U1.F8 U1.G1 U1.G8 U1.H1 U1.H8

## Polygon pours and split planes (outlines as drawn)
GND on Bottom Layer "BOTTOM_LAYER_GND_P005" (solid, pour order 5): 0,790 0,0 790,0 790,790
GND on Top Layer "TOP_LAYER_GND_P002" (solid, pour order 2): 0,790 0,0 790,0 790,790
VDD_3V3_SYS on PWR/GND2 "PWR/GND2_VDD_3V3_SYS_P001" (solid, pour order 1): 0,790 0,0 790,0 790,790
GND on GND1 "GND1_GND_P000" (solid, pour order 0): 0,790 0,0 790,0 790,790
GND on Signal Layer 2 "SIGNAL_LAYER_2_GND_P004" (solid, pour order 4): 0,790 0,0 790,0 790,790
GND on Signal Layer 1 "SIGNAL_LAYER_1_GND_P003" (solid, pour order 3): 24,790 24,0 790,0 790,790

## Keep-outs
Keep-Out Layer:
  text ".Layer_Name" at 577,-858.49 h60

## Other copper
Top Layer:
  text ".Layer_Name" at 577,-858.49 h60
Bottom Layer:
  text ".Layer_Name" at 577,-858.49 h60

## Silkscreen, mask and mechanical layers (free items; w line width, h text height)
Top Overlay:
  text ".Layer_Name" at 577,-858.49 h60
Bottom Overlay:
  text ".Layer_Name" at 577,-858.49 h60
Top Paste:
  text ".Layer_Name" at 577,-858.49 h60
Bottom Paste:
  text ".Layer_Name" at 577,-858.49 h60
Top Solder:
  text ".Layer_Name" at 577,-858.49 h60
  text ".Layer_Name" at 577,-858.49 h60
Bottom Solder:
  text ".Layer_Name" at 577,-858.49 h60
Drill Guide:
  text ".Layer_Name" at 577,-858.49 h60
M1 Board Outline:
  the board outline again, w10
  text ".Layer_Name" at 577,-858.49 h60
M2 Board Dimensions:
  rectangle: 0,-275 125,-150
  rectangle: 125,-400 500,-275
  lines w7: 0,-275 1000,-275 ; 125,-400 125,-150 ; 250,-400 250,-150 ; 500,-400 500,-150 ; 750,-400 750,-150 ; 0,-400 1000,-400 1000,-150 0,-150 0,-400
  text ".Layer_Name" at 577,-858.49 h60
M3 3D STEP Top:
  text ".Layer_Name" at 577,-858.49 h60
M4 3D STEP Bottom:
  text ".Layer_Name" at 577,-858.49 h60
M5 Assembly Top:
  lines w10: -292,-930.17 6308,-930.17 ; -292,-726.83 6310,-726.83 ; -292,-523.5 -292,-1133.5 3713,-1133.5 6310,-1133.5 6310,-523.5 -291.5,-523.5 -291.5,-1133.5 1284,-1133.5 ; 2173,-1133.5 2173,-523.5 ; 3440,-726.83 3440,-523.5 ; 4280,-726.83 4280,-523.5 ; 4902,-1140 4902,-937.17
  text "COMPONENTS MARKED 'DNP' SHOULD NOT BE POPULATED." at 1153.5,-318.5 h60
  text "ASSEMBLY VARIANT:" at 1153,-434 h60
  text ".VariantName" at 2189,-434 h60
  text "PCB VIEWED FROM TOP SIDE" at -228.5,-655.67 h60
  text "BOARD #:" at 2248,-655.67 h60
  text ".PRJ_Number" at 2793.5,-655.67 h60
  text "REV:" at 3638,-655.67 h60
  text ".PCB_Rev" at 3929.5,-655.67 h60
  text "SVN REV:" at 4476,-655.67 h60
  text ".VersionControl_RevNumber" at 4982,-655.67 h60
  text "TID #:" at 2248,-859 h60
  text ".TID" at 2793.5,-859 h60
  text "PLOT NAME =" at -228.5,-1064.34 h60
  text ".plot_File_Name" at 577,-1064.34 h60
  text "GENERATED    :" at 2250,-1064.34 h60
  text ".Print_Date" at 3119.5,-1064.34 h60
  text ".Print_Time" at 3848.5,-1064.34 h60
  text "TEXAS INSTRUMENTS" at 5113,-1064.34 h60
M6 Assembly Bottom:
  lines w10: -292.5,-727.33 6309.5,-727.33 ; -290.5,-930.67 6309.5,-930.67 ; 1115.5,-1140.5 1115.5,-937.67 ; 1737.5,-727.33 1737.5,-524 ; 2577.5,-727.33 2577.5,-524 ; 3844.5,-1134 3844.5,-524 ; 4733.5,-1134 6309,-1134 6309,-524 -292.5,-524 -292.5,-1134 2304.5,-1134 6309.5,-1134 6309.5,-524
  text "COMPONENTS MARKED 'DNP' SHOULD NOT BE POPULATED." at 6102,-318 h60
  text ".VariantName" at 5058,-434 h60
  text "ASSEMBLY VARIANT:" at 6097,-434 h60
  text ".VersionControl_RevNumber" at 1035.5,-656.17 h60
  text "SVN REV:" at 1541.5,-656.17 h60
  text ".PCB_Rev" at 2088,-656.17 h60
  text "REV:" at 2379.5,-656.17 h60
  text ".PRJ_Number" at 3224,-656.17 h60
  text "BOARD #:" at 3769.5,-656.17 h60
  text "PCB VIEWED FROM BOTTOM SIDE" at 6246,-656.17 h60
  text ".TID" at 3224,-859.5 h60
  text "TID #:" at 3769.5,-859.5 h60
  text "TEXAS INSTRUMENTS" at 904.5,-1064.84 h60
  text ".Print_Time" at 2169,-1064.84 h60
  text ".Print_Date" at 2898,-1064.84 h60
  text "GENERATED    :" at 3767.5,-1064.84 h60
  text ".plot_File_Name" at 5440.5,-1064.84 h60
  text "PLOT NAME =" at 6246,-1064.84 h60
M9 Title Sheet:
  drawing of 57 lines, arcs and shapes, not listed
  text "1" at 739.84,8036.5 h70
  text "2" at 3235.5,8036.5 h70
  text "3" at 5724.84,8036.5 h70
  text "4" at 8231.51,8036.5 h70
  text "5" at 10730.5,8036.5 h70
  text "6" at 13235.5,8036.5 h70
  text "A" at -416.5,6893.5 h70
  text "A" at 14383.5,6893.5 h70
  text "B" at -416.5,4513.5 h70
  text "B" at 14383.5,4513.5 h70
  text "C" at -416.5,2138.5 h70
  text "C" at 14383.5,2138.5 h70
  text "PROJECT TITLE:" at 11343.5,277.5 h45
  text ".PRJ_Title" at 11393.5,144.17 h70
  text "DESIGNED FOR:" at 11343.5,-23.5 h45
  text ".PRJ_Customer" at 11393.5,-163.5 h70
  text "D" at -416.5,-231.5 h70
  text "D" at 14383.5,-231.5 h70
  text "FILE NAME:" at 11343.5,-323.5 h45
  text ".PCB_File_Name_No_Path" at 11393.5,-443.5 h70
  text "Texas Instruments (TI) and/or its licensors do not warrant the accuracy or completeness of this specification" at 6374,-605.34 h45
  text "ENGINEER:" at 11343.5,-613.5 h45
  text "LAYOUT BY:" at 12848.5,-613.5 h45
  text "or any information contained therein. TI and/or its licensors do not warrant that this design will meet" at 6329.01,-718 h45
  text ".PRJ_Engineer" at 11393.5,-768.49 h70
  text ".PCB_Layout" at 12899,-768.49 h70
  text "the specifications, will be suitable for your application or fit for any particular purpose, or will operate in" at 6329.01,-830.67 h45
  text ".Layer_Name" at 577,-858.49 h60
  text "ALTIUM DESIGNER VERSION:" at 12848.5,-923.5 h45
  text "an implementation. TI and/or its licensors do not warrant that the design is production worthy. You should" at 6329.01,-943.33 h45
  text "completely validate and test your design implementation to confirm the system functionality for your application." at 6374,-1056 h45
  text ".print_Scale" at 11393.5,-1056.83 h70
  text ".Application_BuildNumber" at 12899,-1056.83 h70
  text "1" at 739.84,-1263.5 h70
  text "2" at 3235.5,-1263.5 h70
  text "3" at 5724.84,-1263.5 h70
  text "4" at 8231.51,-1263.5 h70
  text "5" at 10730.5,-1263.5 h70
  text "6" at 13235.5,-1263.5 h70
M10 Fab Notes:
  drawing of 189 lines, arcs and shapes, not listed
  text "DESIGN INFORMATION" at 12382.02,6356.17 h60
  text "MIN. TRACK WIDTH:" at 11737.46,6224.05 h60
  text "8" at 12833.7,6224.05 h60
  text "MIL" at 12988.46,6224.05 h60
  text "7.874" at 12667.32,6102.36 h60
  text "MIN. CLEARANCE:" at 11737.46,6099.92 h60
  text "MIL" at 12988.46,6099.92 h60
  text "MIN. VIA PAD SIZE:" at 11737.46,5975.8 h60
  text "24" at 12803.71,5975.8 h60
  text "MIL" at 12988.46,5975.8 h60
  text "0.05mm (2MIL)" at 12432.46,5845.9 h60
  text "MINIMUM ANNULAR RING" at 11408.23,5837.67 h60
  text "EXTERNAL" at 13140.46,5837.67 h60
  text "PER" at 11608.23,5727.55 h60
  text "IPC-D-275 CLASS 2 LEVEL C" at 11828.23,5727.54 h60
  text "MIL, HOLES" at 13316.46,5627.07 h60
  text "+/-" at 12924,5618.48 h60
  text "+/-" at 13778,5618.48 h60
  text "REGISTRATION TOLERANCES:" at 11408.23,5617.42 h60
  text "METAL" at 12608,5617.42 h60
  text "5" at 13184.2,5617.42 h60
  text "3" at 14017.2,5617.42 h60
  text "MIL" at 14133.46,5617.42 h60
  text "HOLE SIZE TOLERANCE (UNLESS OTHERWISE SPECIFIED):" at 11408.23,5519.1 h60
  text "+/-" at 13778,5516.23 h60
  text "3" at 14017.2,5515.17 h60
  text "MIL" at 14133.46,5515.17 h60
  text "MATERIAL:" at 11333.46,5377.52 h60
  text "FR-4 High Tg" at 12319.9,5249 h60
  text "X" at 12175.46,5241.01 h60
  text "FR-408" at 11754.46,5236.49 h60
  text "OTHER" at 13242.46,5236.49 h60
  text "62 MIL (1.6mm) +/-10%" at 12074.56,5093.46 h60
  text "X" at 11954.46,5091.01 h60
  text "THICKNESS:" at 11408.23,5085.24 h60
  text "OTHER" at 13359.46,5085.24 h60
  text "TOLERANCE:" at 11408.23,4946.92 h60
  text "X" at 12256.46,4946.92 h60
  text "ANSI IPC-6012 TYPE 3 CLASS 2" at 12434.48,4946.92 h60
  text "OTHER +/-" at 12434.46,4802.73 h60
  text "BOW & TWIST:" at 11408.23,4657.54 h60
  text "X" at 12256.46,4657.54 h60
  text "ANSI IPC-6012 TYPE 3 CLASS 2" at 12434.48,4657.54 h60
  text "OTHER +/-" at 12434.46,4510.85 h60
  text "DRILLING:" at 11333.46,4380.23 h60
  text "NC_DRILL FILES" at 13094.46,4275.04 h60
  text "REFERENCE:" at 11408.23,4271.1 h60
  text "X" at 12065.46,4271.01 h60
  text "AS SHOWN" at 12243.46,4271.1 h60
  text "X" at 12966.46,4271.1 h60
  text "OTHER" at 13392.46,4128.85 h60
  text "PTH COPPER THICKNESS:" at 11407.91,4125.32 h60
  text "X" at 12547.14,4125.32 h60
  text "20-30 um" at 12675.14,4125.32 h60
  text "BOARD FINISH:" at 11333.46,3977.73 h60
  text "SILKSCREEN:" at 11488.68,3867.6 h60
  text "X" at 12446.46,3867.6 h60
  text "TOP" at 12563.46,3867.6 h60
  text "X" at 12956.46,3867.6 h60
  text "BOTTOM" at 13074.46,3867.6 h60
  text "SILKSCREEN COLOR:" at 11488.68,3712.41 h60
  text "X" at 12445.46,3712.41 h60
  text "WHITE" at 12563.46,3712.41 h60
  text "OTHER" at 13074.46,3712.41 h60
  text "X" at 12576.46,3568.96 h60
  text "GREEN" at 12694.46,3568.96 h60
  text "OTHER" at 13312.46,3568.96 h60
  text "SOLDER RESIST COLOR:" at 11488.68,3562.1 h60
  text "X" at 12576.46,3414.71 h60
  text "MATTE" at 12694.46,3414.71 h60
  text "SEMI-GLOSS" at 13312,3414.07 h60
  text "IMMERSION GOLD (ENIG)" at 12394.46,3241.94 h60
  text "ENEPIG" at 13732,3234.72 h60
  text "SURFACE FINISH:" at 11333.46,3233.72 h60
  text "X" at 12216.46,3233.72 h60
  text "IMM. TIN/SILVER OR EQUIV" at 11663,3096.4 h60
  text "OTHER" at 13094.46,3092.47 h60
  text "ARRAY/PANEL:" at 11333.46,2937.09 h60
  text "CUT AND TRIM PER M1 BOARD OUTLINE" at 12394.46,2928.87 h60
  text "N.C. ROUTE" at 12394.46,2792.9 h60
  text "X" at 13082.46,2792.9 h60
  text "V. SCORE" at 13260.46,2792.9 h60
  text "CERTIFICATION:" at 11333.46,2663.77 h60
  text "MATERIALS AND WORKMANSHIP FOR ALL PCBS" at 12058.46,2663.77 h60
  text "TO MEET OR EXCEED THE REQUIREMENTS OF:" at 12058.46,2569.71 h60
  text "X" at 11695.97,2441.08 h60
  text "ANSI IPC-A-600F CLASS ->" at 11823.96,2441.08 h60
  text "X" at 13471.97,2441.08 h60
  text "2" at 13581.96,2441.08 h60
  text "1" at 13266.96,2439.58 h60
  text "3" at 13935.96,2439.58 h60
  text "X" at 12507.97,2293.39 h60
  text "RoHS" at 12635.96,2293.39 h60
  text "OTHER" at 13280.36,2293.39 h60
  text "PER ORDER" at 13677.42,2293.39 h60
  text "ALL BOARDS MUST MEET OR EXCEED UL94-V0 REQUIREMENTS." at 11361,2139.57 h60
  text "PCB MUST BEAR THE UL94V-0 UL REGISTERED MATERIAL ID NUMBER" at 11361,2023.5 h60
  text "ADDITIONAL REQUIREMENTS:" at 11333.46,1854.08 h60
  text "MICROSECTION:" at 11408.23,1746.95 h60
  text "YES" at 12313.96,1746.95 h60
  text "REQUIRED" at 13175.46,1602.62 h60
  text "BARE BOARD ELEC. TEST:" at 11408.23,1599.76 h60
  text "NONE" at 12713.96,1599.76 h60
  text "X" at 13057.46,1599.76 h60
  text "PER ORDER" at 13767.46,1599.76 h60
  text "XX MIL VIAS REQUIRE NON-CONDUCTIVE FILL AND PLANARIZE" at 11576.38,1394.82 h59
  text "XX MIL VIAS REQUIRE CONDUCTIVE FILL AND PLANARIZE" at 11584.38,1290.84 h60
  text "OUTER XX MIL TRACES REQUIRE 50 OHM SINGLE-ENDED IMPEDANCE" at 11583.39,1127.46 h58
  text "LAYER 2 & 3 (INNER LAYERS) XX MIL WIDE, XX MIL SPACE / TRACES REQUIRE 100 OHM DIFFERENTIAL IMPEDANCE" at 11575.39,891.74 h60
  text ".Layer_Name" at 577,-858.49 h60
M11 Gerber Information:
  lines w10: -292,-930.17 6308,-930.17 ; -292,-726.83 6310,-726.83 ; -292,-523.5 -292,-1133.5 3713,-1133.5 6310,-1133.5 6310,-523.5 -291.5,-523.5 -291.5,-1133.5 1284,-1133.5 ; 2173,-1133.5 2173,-523.5 ; 3440,-726.83 3440,-523.5 ; 4280,-726.83 4280,-523.5 ; 4902,-1140 4902,-937.17
  text "ALL ARTWORK VIEWED FROM TOP SIDE" at -228.5,-655.67 h60
  text "BOARD #:" at 2248,-655.67 h60
  text ".PRJ_Number" at 2793.5,-655.67 h60
  text "REV:" at 3638,-655.67 h60
  text ".PCB_Rev" at 3929.5,-655.67 h60
  text "SVN REV:" at 4476,-655.67 h60
  text ".VersionControl_RevNumber" at 4982,-655.67 h60
  text "LAYER NAME =" at -228.5,-858.49 h60
  text "TID #:" at 2248,-859 h60
  text ".TID" at 2793.5,-859 h60
  text "PLOT NAME =" at -228.5,-1064.34 h60
  text ".plot_File_Name" at 577,-1064.34 h60
  text "GENERATED    :" at 2250,-1064.34 h60
  text ".Print_Date" at 3119.5,-1064.34 h60
  text ".Print_Time" at 3848.5,-1064.34 h60
  text "TEXAS INSTRUMENTS" at 5113,-1064.34 h60
M12 Stackup:
  drawing of 399 lines, arcs and shapes, not listed
  text "Layer" at 5985.46,7482.01 h60
  text "Name" at 6395.38,7482.01 h60
  text "Material" at 7335.12,7482.01 h60
  text "Thickness" at 8194.88,7482.01 h60
  text "Constant" at 8844.72,7482.01 h60
  text "Board Layer Stack" at 9414.58,7482.01 h60
  text "Top Overlay" at 6395.38,7362.01 h60
  text "Top Solder" at 6395.38,7242.01 h60
  text "Solder Resist" at 7335.12,7242.01 h60
  text "0.40mil" at 8194.88,7242.01 h60
  text "3.5" at 8844.72,7242.01 h60
  text "1" at 5985.46,7122.01 h60
  text "Top Layer" at 6395.38,7122.01 h60
  text "0.69mil" at 8194.88,7122.01 h60
  text "Dielectric 1" at 6395.38,7002.01 h60
  text "FR-4" at 7335.12,7002.01 h60
  text "3.70mil" at 8194.88,7002.01 h60
  text "4.1" at 8844.72,7002.01 h60
  text "2" at 5985.46,6882.01 h60
  text "GND1" at 6395.38,6882.01 h60
  text "0.69mil" at 8194.88,6882.01 h60
  text "Dielectric 3" at 6395.38,6762.01 h60
  text "PP-006" at 7335.12,6762.01 h60
  text "2.80mil" at 8194.88,6762.01 h60
  text "4.1" at 8844.72,6762.01 h60
  text "3" at 5985.46,6642.01 h60
  text "Signal Layer 1" at 6395.38,6642.01 h60
  text "CF-004" at 7335.12,6642.01 h60
  text "0.69mil" at 8194.88,6642.01 h60
  text "Dielectric1" at 6395.38,6522.01 h60
  text "FR-4" at 7335.12,6522.01 h60
  text "48.00mil" at 8194.88,6522.01 h60
  text "4.8" at 8844.72,6522.01 h60
  text "4" at 5985.46,6402.01 h60
  text "Signal Layer 2" at 6395.38,6402.01 h60
  text "CF-004" at 7335.12,6402.01 h60
  text "0.69mil" at 8194.88,6402.01 h60
  text "Dielectric 4" at 6395.38,6282.01 h60
  text "PP-006" at 7335.12,6282.01 h60
  text "2.80mil" at 8194.88,6282.01 h60
  text "4.1" at 8844.72,6282.01 h60
  text "5" at 5985.46,6162.01 h60
  text "PWR/GND2" at 6395.38,6162.01 h60
  text "0.69mil" at 8194.88,6162.01 h60
  text "Dielectric 2" at 6395.38,6042.01 h60
  text "FR-4" at 7335.12,6042.01 h60
  text "3.70mil" at 8194.88,6042.01 h60
  text "4.1" at 8844.72,6042.01 h60
  text "6" at 5985.46,5922.01 h60
  text "Bottom Layer" at 6395.38,5922.01 h60
  text "0.69mil" at 8194.88,5922.01 h60
  text "Bottom Solder" at 6395.38,5802.01 h60
  text "Solder Resist" at 7335.12,5802.01 h60
  text "0.40mil" at 8194.88,5802.01 h60
  text "3.5" at 8844.72,5802.01 h60
  text "Bottom Overlay" at 6395.38,5682.01 h60
  text ".Layer_Name" at 577,-858.49 h60
M13 Component Bodies Top:
  text ".Layer_Name" at 577,-858.49 h60
M14 Component Bodies Bottom:
  text ".Layer_Name" at 577,-858.49 h60
M15 Courtyards Top:
  text ".Layer_Name" at 577,-858.49 h60
M16 Courtyards Bottom:
  text ".Layer_Name" at 577,-858.49 h60
Drill Drawing:
  circle w10: c5363.72,3290.28 r27.63
  lines w10: 5336.09,3014.02 5391.34,3014.02 5391.34,3069.27 5336.09,3069.27 5336.09,3014.02 ; 5336.09,3193.59 5391.34,3193.59 5363.72,3138.34 5336.09,3193.59
  lines w12: 5286,2976.72 8517.49,2976.72 ; 5286,3349.68 8517.49,3349.68 ; 5623.86,2852.4 5623.86,3474 ; 5955.86,2852.4 5955.86,3474 ; 6592.43,2852.4 6592.43,3474 ; 6851.57,2852.4 6851.57,3474 ; 7226.72,2852.4 7226.72,3474 ; 7951.05,2852.4 7951.05,3474 ; 5286,2852.4 8517.49,2852.4 8517.49,3474 5286,3474 5286,2852.4
  text "Symbol" at 5360.59,3386.98 h72
  text "Quantity" at 5661.16,3386.98 h72
  text "Finished Hole Size" at 5993.16,3386.98 h72
  text "Plated" at 6629.72,3386.98 h72
  text "Hole Type" at 6888.86,3386.98 h72
  text "Drill Layer Pair" at 7264.02,3386.98 h72
  text "Hole Tolerance" at 7988.35,3386.98 h72
  text "37" at 5661.16,3262.66 h60
  text "7.87mil (0.200mm)" at 5993.16,3262.66 h60
  text "PTH" at 6629.72,3262.66 h60
  text "Round" at 6888.86,3262.66 h60
  text "Top Layer - Bottom Layer" at 7264.02,3262.66 h60
  text "65" at 5661.16,3138.34 h60
  text "10.00mil (0.254mm)" at 5993.16,3138.34 h60
  text "PTH" at 6629.72,3138.34 h60
  text "Round" at 6888.86,3138.34 h60
  text "Top Layer - Bottom Layer" at 7264.02,3138.34 h60
  text "56" at 5661.16,3014.02 h60
  text "30.00mil (0.762mm)" at 5993.16,3014.02 h60
  text "PTH" at 6629.72,3014.02 h60
  text "Round" at 6888.86,3014.02 h60
  text "Top Layer - Bottom Layer" at 7264.02,3014.02 h60
  text "158 Total" at 5661.16,2889.7 h60
  text ".Layer_Name" at 577,-858.49 h60
M17 Embedded Cavity:
  text ".Layer_Name" at 577,-858.49 h60
M18 Embedded Assembly:
  text ".Layer_Name" at 577,-858.49 h60
M19 Embedded Keepout:
  text ".Layer_Name" at 577,-858.49 h60

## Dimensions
0,-400 to 1000,-400 on M2 Board Dimensions
0,0 to 0,790 on M2 Board Dimensions
0,0 to 790,0 on M2 Board Dimensions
